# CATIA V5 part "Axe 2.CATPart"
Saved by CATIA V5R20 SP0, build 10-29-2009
Part number: Axe 2
Bounding box of the stored display mesh (mm): x -5.41 to 1.59, y 43.5 to 50.5, z -18 to -3.5
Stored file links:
  E:\Boulot\SeaTech\2eme ANNEE\FabricationAdditive\TP_MOSM_CREM\Projet Sauterelle de serrage\CAO Assemblage Sauterelle\Axe 2.CATPart
  E:\Boulot\SeaTech\2eme ANNEE\FabricationAdditive\TP_MOSM_CREM\Projet Sauterelle de serrage\CAO Assemblage Sauterelle\Sauterelle_horizontale_05120-06.CATPart
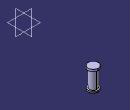
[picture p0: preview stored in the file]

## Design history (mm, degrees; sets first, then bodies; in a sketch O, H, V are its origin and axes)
Body1 (main body)
  Solid1 "05120-06_3": solid without history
